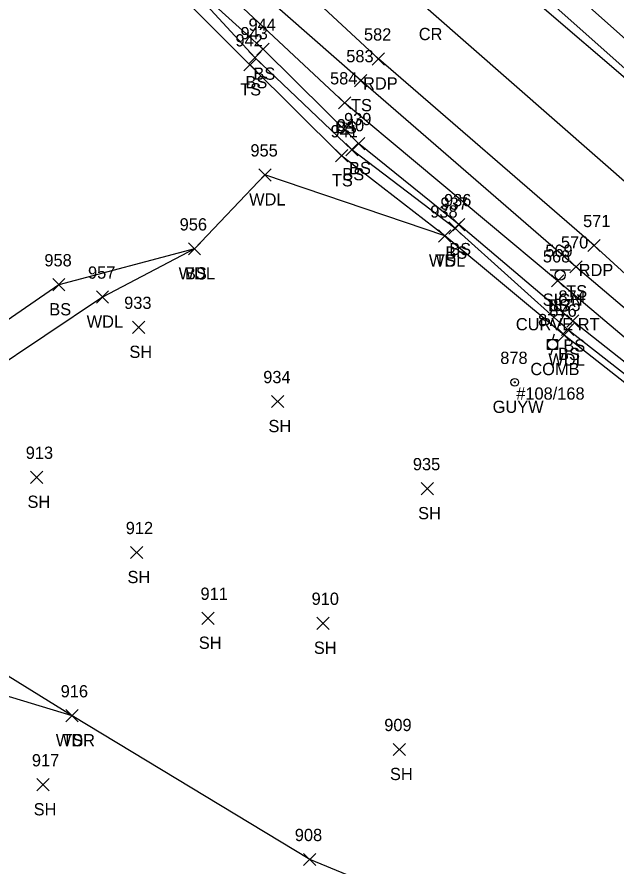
# Model space of a CAD drawing. Extents: x 1879695 to 1880991, y 836466 to 845172.
# Drawn here: x 1879991.4 to 1880089.2, y 844083.5 to 844222.2 of the extents above; entities that cross this region are included whole.
import ezdxf

# ---------------------------------------------------------------- set-up
doc = ezdxf.new("R2010")
doc.units = 0
for name, color, linetype in [('L_A', 7, 'Continuous'), ('L_I', 7, 'Continuous'), ('L_TIC', 7, 'Continuous'), ('LAWA', 7, 'Continuous'), ('LELB', 7, 'Continuous'), ('P_A', 7, 'Continuous'), ('P_I', 7, 'Continuous'), ('P_TIC', 7, 'Continuous'), ('PET', 7, 'Continuous'), ('PRC', 7, 'Continuous'), ('RGR', 7, 'Continuous'), ('S_A', 7, 'Continuous'), ('S_C', 7, 'Continuous'), ('S_I', 7, 'Continuous'), ('SSGN', 7, 'Continuous'), ('U_A', 7, 'Continuous'), ('U_C', 7, 'Continuous'), ('U_I', 7, 'Continuous'), ('UP', 7, 'Continuous'), ('UPGW', 7, 'Continuous')]:
    doc.layers.add(name, color=color, linetype=linetype)

msp = doc.modelspace()

# ---------------------------------------------------------------- linework, layer by layer
at = {"layer": 'L_TIC'}
for points in [[(1880030.58, 844215.92), (1880032.58, 844217.92)], [(1880032.58, 844215.92), (1880030.58, 844217.92)], [(1880029.27, 844214.53), (1880031.27, 844216.53)], [(1880031.27, 844214.53), (1880029.27, 844216.53)], [(1880028.44, 844213.36), (1880030.44, 844215.36)], [(1880030.44, 844213.36), (1880028.44, 844215.36)], [(1880046.53, 844210.78), (1880048.53, 844212.78)], [(1880048.53, 844210.78), (1880046.53, 844212.78)], [(1880043.89, 844207.16), (1880045.89, 844209.16)], [(1880045.89, 844207.16), (1880043.89, 844209.16)], [(1880046.18, 844200.5), (1880048.18, 844202.5)], [(1880048.18, 844200.5), (1880046.18, 844202.5)], [(1880045.08, 844199.5), (1880047.08, 844201.5)], [(1880047.08, 844199.5), (1880045.08, 844201.5)], [(1880043.41, 844198.51), (1880045.41, 844200.51)], [(1880045.41, 844198.51), (1880043.41, 844200.51)], [(1880030.89, 844195.39), (1880032.89, 844197.39)], [(1880032.89, 844195.39), (1880030.89, 844197.39)], [(1880061.9, 844186.7), (1880063.9, 844188.7)], [(1880063.9, 844186.7), (1880061.9, 844188.7)], [(1880062.54, 844187.27), (1880064.54, 844189.27)], [(1880064.54, 844187.27), (1880062.54, 844189.27)], [(1880060.24, 844185.41), (1880062.24, 844187.41)], [(1880062.24, 844185.41), (1880060.24, 844187.41)], [(1880060.24, 844185.41), (1880062.24, 844187.41)], [(1880062.24, 844185.41), (1880060.24, 844187.41)], [(1880019.4, 844183.31), (1880021.4, 844185.31)], [(1880021.4, 844183.31), (1880019.4, 844185.31)], [(1880019.4, 844183.31), (1880021.4, 844185.31)], [(1880021.4, 844183.31), (1880019.4, 844185.31)], [(1880081.65, 844180.38), (1880083.65, 844182.38)], [(1880083.65, 844180.38), (1880081.65, 844182.38)], [(1880078.67, 844178.09), (1880080.67, 844180.09)], [(1880080.67, 844178.09), (1880078.67, 844180.09)], [(1879997.26, 844177.45), (1879999.26, 844179.45)], [(1879999.26, 844177.45), (1879997.26, 844179.45)], [(1880004.38, 844175.44), (1880006.38, 844177.44)], [(1880006.38, 844175.44), (1880004.38, 844177.44)], [(1880081.15, 844171.53), (1880083.15, 844173.53)], [(1880083.15, 844171.53), (1880081.15, 844173.53)], [(1880010.28, 844170.5), (1880012.28, 844172.5)], [(1880012.28, 844170.5), (1880010.28, 844172.5)], [(1880080.3, 844170.15), (1880082.3, 844172.15)], [(1880082.3, 844170.15), (1880080.3, 844172.15)], [(1880079.73, 844169.23), (1880081.73, 844171.23)], [(1880081.73, 844169.23), (1880079.73, 844171.23)], [(1880032.98, 844158.38), (1880034.98, 844160.38)], [(1880034.98, 844158.38), (1880032.98, 844160.38)], [(1879993.65, 844146.02), (1879995.65, 844148.02)], [(1879995.65, 844146.02), (1879993.65, 844148.02)], [(1880057.4, 844144.16), (1880059.4, 844146.16)], [(1880059.4, 844144.16), (1880057.4, 844146.16)], [(1880009.98, 844133.73), (1880011.98, 844135.73)], [(1880011.98, 844133.73), (1880009.98, 844135.73)], [(1880021.61, 844123), (1880023.61, 844125)], [(1880023.61, 844123), (1880021.61, 844125)], [(1880040.39, 844122.18), (1880042.39, 844124.18)], [(1880042.39, 844122.18), (1880040.39, 844124.18)], [(1879999.41, 844107.08), (1880001.41, 844109.08)], [(1880001.41, 844107.08), (1879999.41, 844109.08)], [(1879999.41, 844107.08), (1880001.41, 844109.08)], [(1880001.41, 844107.08), (1879999.41, 844109.08)], [(1880052.82, 844101.57), (1880054.82, 844103.57)], [(1880054.82, 844101.57), (1880052.82, 844103.57)], [(1879994.66, 844095.81), (1879996.66, 844097.81)], [(1879996.66, 844095.81), (1879994.66, 844097.81)], [(1880038.21, 844083.61), (1880040.21, 844085.61)], [(1880040.21, 844083.61), (1880038.21, 844085.61)], [(1880038.21, 844083.61), (1880040.21, 844085.61)], [(1880040.21, 844083.61), (1880038.21, 844085.61)]]:
    msp.add_lwpolyline(points, dxfattribs=at)
at = {"layer": 'LAWA'}
for points in [[(1880235.36, 844016.97), (1880226.78, 844031.19), (1880215.51, 844044.03), (1880209.22, 844044.19), (1880209.6, 844049.55), (1880199.81, 844058.74), (1880190.2, 844070.4), (1880171.48, 844090.23), (1880169.04, 844093.32), (1880159.9, 844092.48), (1880155.76, 844084.92), (1880148.42, 844091.37), (1880152.26, 844105.95), (1880144.4, 844115.49), (1880125.95, 844132.35), (1880103.11, 844152.62), (1880080.73, 844170.23), (1880061.24, 844186.41), (1880031.89, 844196.39), (1880020.4, 844184.31), (1880005.38, 844176.44), (1879986.51, 844163.82)], [(1880039.21, 844084.61), (1880000.41, 844108.08), (1879965.41, 844118.67), (1879945.04, 844133.71), (1879921.71, 844153.19), (1879911.33, 844144.96)]]:
    msp.add_lwpolyline(points, dxfattribs=at)
at = {"layer": 'LELB'}
for points in [[(1880237.65, 844030.17), (1880225.55, 844045.25), (1880203.19, 844067.94), (1880175.04, 844095.38), (1880141.55, 844124.24), (1880111.59, 844152.12), (1880079.67, 844179.09), (1880044.89, 844208.16), (1880013.5, 844237.54), (1880003.34, 844247.82), (1879979.16, 844270.62), (1879948.51, 844300.87), (1879928.97, 844335.67), (1879901.59, 844373.87), (1879881.39, 844405.75), (1879863.37, 844445.07), (1879846.41, 844479.41), (1879833.35, 844517.23), (1879821, 844560.9), (1879811.24, 844600.26), (1879800.64, 844646.71), (1879794.2, 844680.16), (1879792.03, 844683.6), (1879789.08, 844683.63)], [(1880243.53, 844023.94), (1880226.64, 844046.28), (1880204.68, 844069.12), (1880177.19, 844097.39), (1880144.15, 844127.37), (1880114.34, 844154.46), (1880082.65, 844181.38), (1880047.53, 844211.78), (1880015.32, 844240.12), (1879982.29, 844271.84), (1879951.96, 844303.04), (1879930.28, 844336.91), (1879904.08, 844374.32), (1879883.92, 844406.9), (1879866.98, 844446.02), (1879852.23, 844482.49), (1879838.68, 844519.35), (1879826.86, 844562.48), (1879815.22, 844600.52)], [(1880274.18, 844042.18), (1880252.69, 844068.34), (1880228.42, 844092.99), (1880199.77, 844120.37), (1880165.71, 844151.73), (1880135.43, 844177.69), (1880104.5, 844206.3), (1880070.17, 844236.88), (1880037.83, 844267.79), (1880007.31, 844296.06), (1879981.71, 844326.11), (1879957.94, 844357.83), (1879934.98, 844394.4), (1879917.02, 844424.23)], [(1880061.24, 844186.41), (1880044.41, 844199.51), (1880029.44, 844214.36), (1880014.82, 844229.08), (1880001.48, 844240.9), (1879983.99, 844256.18), (1879963.67, 844277.76), (1879939.18, 844304.48), (1879924.63, 844325.43), (1879894.06, 844369.68)], [(1880208.14, 844057.06), (1880205.3, 844059.71), (1880199.4, 844059.75), (1880191.54, 844071.18), (1880172.4, 844091.6), (1880168.93, 844094.5), (1880159.81, 844093.84), (1880155.76, 844086.44), (1880150.38, 844091.63), (1880154.09, 844106.65), (1880145.11, 844116.32), (1880126.55, 844133.72), (1880103.74, 844153.59), (1880081.3, 844171.15), (1880062.9, 844187.7), (1880046.08, 844200.5), (1880030.27, 844215.53), (1880015.96, 844231.11), (1880002.51, 844242.73), (1879985.64, 844257.52)], [(1880223.61, 844044.33), (1880209.51, 844057.91), (1880192.94, 844072.51), (1880173.59, 844092.48), (1880156.34, 844108.5), (1880145.52, 844117.21), (1880140.19, 844123.17), (1880127.57, 844134.43), (1880104.95, 844154.51), (1880082.15, 844172.53), (1880063.54, 844188.27), (1880047.18, 844201.5), (1880031.58, 844216.92), (1880015.96, 844231.11)], [(1880000.41, 844108.08), (1879970.63, 844126.53), (1879949.63, 844139.05), (1879930.57, 844162.09), (1879904.28, 844177.57), (1879891.68, 844181.68), (1879866.82, 844218.96), (1879857.04, 844216.58), (1879839.4, 844202.83)], [(1880020.4, 844184.31), (1879998.26, 844178.45), (1879985.03, 844169.35), (1879974.27, 844162.51)], [(1880205.14, 844013.35), (1880191.21, 844019.31), (1880170.65, 844024.97), (1880149.68, 844023.18), (1880131.81, 844038.78), (1880122.52, 844049.64), (1880090.54, 844059.6), (1880064.96, 844073.97), (1880039.21, 844084.61)]]:
    msp.add_lwpolyline(points, dxfattribs=at)
at = {"layer": 'P_TIC'}
for points in [[(1880049.42, 844214.32), (1880051.42, 844216.32)], [(1880051.42, 844214.32), (1880049.42, 844216.32)], [(1880084.61, 844183.86), (1880086.61, 844185.86)], [(1880086.61, 844183.86), (1880084.61, 844185.86)]]:
    msp.add_lwpolyline(points, dxfattribs=at)
at = {"layer": 'PET'}
for points in [[(1880269.75, 844039.67), (1880250.27, 844065.9), (1880225.97, 844090.31), (1880195.98, 844117.55), (1880162.1, 844148.13), (1880132.62, 844174.7), (1880101.36, 844203.03), (1880066.94, 844232.59), (1880034.5, 844263.16), (1880004.09, 844293.64), (1879978.17, 844323.39), (1879954.46, 844354.82), (1879930.76, 844391.37), (1879912.37, 844423.12), (1879894.17, 844458.9), (1879879.41, 844492.34), (1879865.46, 844529.81), (1879852.88, 844569.32), (1879843.17, 844608.03)], [(1880246.17, 844024.86), (1880229.35, 844048.54), (1880207.67, 844072.23), (1880179.65, 844099.99), (1880146.48, 844130.19), (1880116.3, 844156.76), (1880085.61, 844184.86), (1880050.42, 844215.32), (1880017.65, 844245.83), (1879986.99, 844277.13), (1879959.04, 844308.59), (1879934.2, 844340.79), (1879910.26, 844378.73), (1879891.14, 844411.43), (1879872.36, 844448.44), (1879856.33, 844484.43), (1879842.37, 844521.56), (1879829.6, 844563.28), (1879820.43, 844602.23)]]:
    msp.add_lwpolyline(points, dxfattribs=at)
at = {"layer": 'PRC'}
msp.add_lwpolyline([(1880256.85, 844032.04), (1880238.91, 844056.2), (1880216.7, 844080.65), (1880187.27, 844108.93), (1880154.23, 844138.82), (1880124.19, 844165.48), (1880092.74, 844193.41), (1880058.56, 844223.39), (1880025.99, 844253.92), (1879995.14, 844285.41), (1879968.79, 844316.24), (1879945.09, 844347.91), (1879920.67, 844385.19), (1879902.45, 844417.14), (1879883.72, 844454.21), (1879868.53, 844488.38), (1879854.47, 844526.01), (1879841.81, 844566.38), (1879832.13, 844605)], dxfattribs=at)
at = {"layer": 'RGR'}
msp.add_lwpolyline([(1880270.9, 844040.93), (1880251.09, 844066.69), (1880226.93, 844091.38), (1880197.34, 844118.12), (1880162.87, 844149.15), (1880133.45, 844175.62), (1880101.92, 844203.72), (1880067.67, 844234.21), (1880035.3, 844264.37), (1880005.3, 844294.8), (1879979.45, 844324.37), (1879956.29, 844356.24), (1879932.57, 844392.56), (1879914.54, 844423.96), (1879896.38, 844459.86), (1879881.66, 844493.03), (1879867.6, 844530.61), (1879855.21, 844570.01), (1879845.36, 844608.98)], dxfattribs=at)
at = {"layer": 'SSGN'}
for p, q in [((1880078.44, 844180.87), (1880081.77, 844180.87)), ((1880080.08, 844180.03), (1880080.08, 844180.03))]:
    msp.add_line(p, q, dxfattribs=at)
msp.add_circle((1880080.08, 844180.03), 0.833, dxfattribs=at)
at = {"layer": 'UP'}
for p, q in [((1880079.08, 844170.36), (1880078.83, 844169.52)), ((1880077.99, 844167.86), (1880077.99, 844169.52)), ((1880077.99, 844169.52), (1880079.66, 844169.52)), ((1880078.83, 844168.69), (1880078.83, 844168.69)), ((1880079.66, 844169.52), (1880079.66, 844167.86)), ((1880079.66, 844167.86), (1880077.99, 844167.86)), ((1880078.58, 844167.02), (1880078.83, 844167.86))]:
    msp.add_line(p, q, dxfattribs=at)
msp.add_circle((1880078.83, 844168.69), 0.833, dxfattribs=at)
at = {"layer": 'UPGW'}
for radius in [0.625, 0.0833]:
    msp.add_circle((1880072.66, 844162.52), radius, dxfattribs=at)

# ---------------------------------------------------------------- texts
at = {"layer": 'L_A'}
for s, p in [('BS', (1880030.02, 844211.92)), ('BS', (1880028.71, 844210.53)), ('TS', (1880027.85, 844209.36)), ('TS', (1880045.94, 844206.78)), ('BS', (1880043.33, 844203.16)), ('BS', (1880045.62, 844196.5)), ('TS', (1880042.82, 844194.51)), ('BS', (1880044.52, 844195.5)), ('WDL', (1880029.31, 844191.39)), ('BS', (1880061.98, 844183.27)), ('BS', (1880061.34, 844182.7)), ('WDL', (1880058.66, 844181.41)), ('TS', (1880059.65, 844181.41)), ('WDL', (1880017.81, 844179.31)), ('BS', (1880018.84, 844179.31)), ('TS', (1880081.06, 844176.38)), ('BS', (1880078.11, 844174.09)), ('BS', (1879996.7, 844173.45)), ('WDL', (1880002.8, 844171.44)), ('BS', (1880080.6, 844167.53)), ('SH', (1880009.77, 844166.5)), ('BS', (1880079.74, 844166.15)), ('WDL', (1880078.15, 844165.23)), ('SH', (1880032.47, 844154.38)), ('SH', (1879993.14, 844142.02)), ('SH', (1880056.89, 844140.16)), ('SH', (1880009.46, 844129.73)), ('SH', (1880021.1, 844119)), ('SH', (1880039.88, 844118.18)), ('WDR', (1879997.77, 844103.08)), ('TS', (1879998.82, 844103.08)), ('SH', (1880052.3, 844097.57)), ('SH', (1879994.15, 844091.81))]:
    msp.add_text(s, height=2, dxfattribs=at).set_placement(p)
at = {"layer": 'L_I'}
for s, p in [('944', (1880029.22, 844219.92)), ('943', (1880027.91, 844218.53)), ('942', (1880027.08, 844217.36)), ('583', (1880045.17, 844214.78)), ('584', (1880042.52, 844211.16)), ('939', (1880044.81, 844204.5)), ('940', (1880043.63, 844203.5)), ('941', (1880042.61, 844202.51)), ('955', (1880029.53, 844199.39)), ('937', (1880060.54, 844190.7)), ('936', (1880061.12, 844191.27)), ('938', (1880058.88, 844189.41)), ('938', (1880058.88, 844189.41)), ('956', (1880017.98, 844187.31)), ('956', (1880017.98, 844187.31)), ('570', (1880080.2, 844184.38)), ('568', (1880077.26, 844182.09)), ('958', (1879995.9, 844181.45)), ('957', (1880003.02, 844179.44)), ('874', (1880079.79, 844175.53)), ('933', (1880008.92, 844174.5)), ('875', (1880078.93, 844174.15)), ('876', (1880078.31, 844173.23)), ('934', (1880031.62, 844162.38)), ('913', (1879992.86, 844150.02)), ('935', (1880056.04, 844148.16)), ('912', (1880009.18, 844137.73)), ('911', (1880021.38, 844127)), ('910', (1880039.51, 844126.18)), ('916', (1879998.56, 844111.08)), ('916', (1879998.56, 844111.08)), ('909', (1880051.37, 844105.57)), ('917', (1879993.86, 844099.81)), ('908', (1880036.77, 844087.61)), ('908', (1880036.77, 844087.61))]:
    msp.add_text(s, height=2, dxfattribs=at).set_placement(p)
at = {"layer": 'P_A'}
for s, p in [('CR', (1880057, 844218.39)), ('RDP', (1880047.91, 844210.32)), ('RDP', (1880083.1, 844179.86))]:
    msp.add_text(s, height=2, dxfattribs=at).set_placement(p)
at = {"layer": 'P_I'}
for s, p in [('582', (1880048.06, 844218.32)), ('571', (1880083.82, 844187.86))]:
    msp.add_text(s, height=2, dxfattribs=at).set_placement(p)
at = {"layer": 'S_A'}
msp.add_text('SIGN', height=2, dxfattribs=at).set_placement((1880077.22, 844175.01))
at = {"layer": 'S_C'}
msp.add_text('CURVE RT', height=2, dxfattribs=at).set_placement((1880072.84, 844171.01))
at = {"layer": 'S_I'}
msp.add_text('569', height=2, dxfattribs=at).set_placement((1880077.65, 844183.01))
at = {"layer": 'U_A'}
for s, p in [('COMB', (1880075.21, 844163.69)), ('GUYW', (1880069.06, 844157.52))]:
    msp.add_text(s, height=2, dxfattribs=at).set_placement(p)
at = {"layer": 'U_C'}
msp.add_text('#108/168', height=2, dxfattribs=at).set_placement((1880072.91, 844159.69))
at = {"layer": 'U_I'}
for s, p in [('877', (1880076.47, 844171.69)), ('878', (1880070.3, 844165.52))]:
    msp.add_text(s, height=2, dxfattribs=at).set_placement(p)

doc.saveas('drawing.dxf')
